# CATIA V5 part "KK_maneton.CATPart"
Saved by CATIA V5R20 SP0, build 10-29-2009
Part number: maneton
Bounding box of the stored display mesh (mm): x 10 to 15, y 78 to 107, z -7 to 7
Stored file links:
  G:\Khaled_CFAO_2011\ST2M\ST2M_GR2\aandujar\Khaled\CAD_thinkMOTION\KK_maneton.CATPart
  G:\Khaled_CFAO_2011\ST2M\ST2M_GR2\aandujar\Khaled\CAD_thinkMOTION\KK_Aandujar.CATProduct
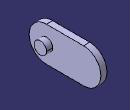
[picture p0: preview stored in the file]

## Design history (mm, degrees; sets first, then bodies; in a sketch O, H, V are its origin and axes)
WSupportSet1: ActiveGrid {3dwsupport RefPoint {point stored without definition}, 3DWOS ({wsupport Support xy-plane, RefPoint {3dwsupport}, GridIn {cartgrid Value 100, Stepbid1 0, Value 100, Stepbid2 0, Direction (1, 0, 0)}, GeometricData ({line type PtDir, Direction (1, 0, 0), Support xy-plane}; {line type PtDir, Direction (0, 1, 0), Support yz-plane})}; {wsupport Support yz-plane, RefPoint {3dwsupport}, GridIn {cartgrid Value 100, Stepbid1 0, Value 100, Stepbid2 0, Direction (0, 1, 0)}, GeometricData ({line type PtDir, Direction (0, 1, 0), Support yz-plane}; {line type PtDir, Direction (0, 0, 1), Support zx-plane})}; {wsupport Support zx-plane, RefPoint {3dwsupport}, GridIn {cartgrid Value 100, Stepbid1 0, Value 100, Stepbid2 0, Direction (0, 0, 1)}, GeometricData ({line type PtDir, Direction (0, 0, 1), Support zx-plane}; {line type PtDir, Direction (1, 0, 0), Support xy-plane})}), GeometricData ({line type PtDir, RefPoint {point stored without definition}, Direction (1, 0, 0), Support xy-plane}; {line type PtDir, RefPoint {point stored without definition}, Direction (0, 1, 0), Support yz-plane}; {line type PtDir, RefPoint {point stored without definition}, Direction (0, 0, 1), Support zx-plane})}
Set1
  Sketch1 on Plane2, origin (10, 0, 0), H (0, 1, 0), V (0, 0, 1)
    construction line L1 (100, 0) -> (85, 0)
    point P1 (100, 0)
    point P2 (85, 0)
    line L2 (100, -7) -> (85, -7)
    line L3 (85, 7) -> (100, 7)
    arc A1 centre (85, 0) radius 7 from (85, -7) to (85, 7) cw
    arc A2 centre (100, 0) radius 7 from (100, 7) to (100, -7) cw
    reference projected point E1 (100, 0) from Point1
    reference projected point E2 (85, 0) from Point2
    distance L1 L2 = 7
    coincidence: P1 H, P1 E1, P2 E2
    horizontal: L1 H
    tangency: A1 L2, A2 L2, A1 L3, A2 L3
Set2
  Plane1 "Plan.Ref4": linked copy from another document
  Plane2 "Plan.Ref3": linked copy from another document
  Point1: linked copy from another document
  Point2: linked copy from another document
  Line1 "Axe_maneton_biellette": linked copy from another document
Body1 (main body)
  Pad1: profile Sketch1, direction (1, 0, 0), length 2.5
  Sketch2 on end face of Pad1, origin (12.5, 0, 0), H (0, 1, 0), V (0, 0, 1)
    circle A1 centre (85, 0) radius 2.5
    point P1 (85, 0)
    reference projected point E1 (85, 0) from Line1
    radius A1 = 2.5
    coincidence: E1 P1
  Pad2: profile Sketch2, direction (1, 0, 0), length 2.5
